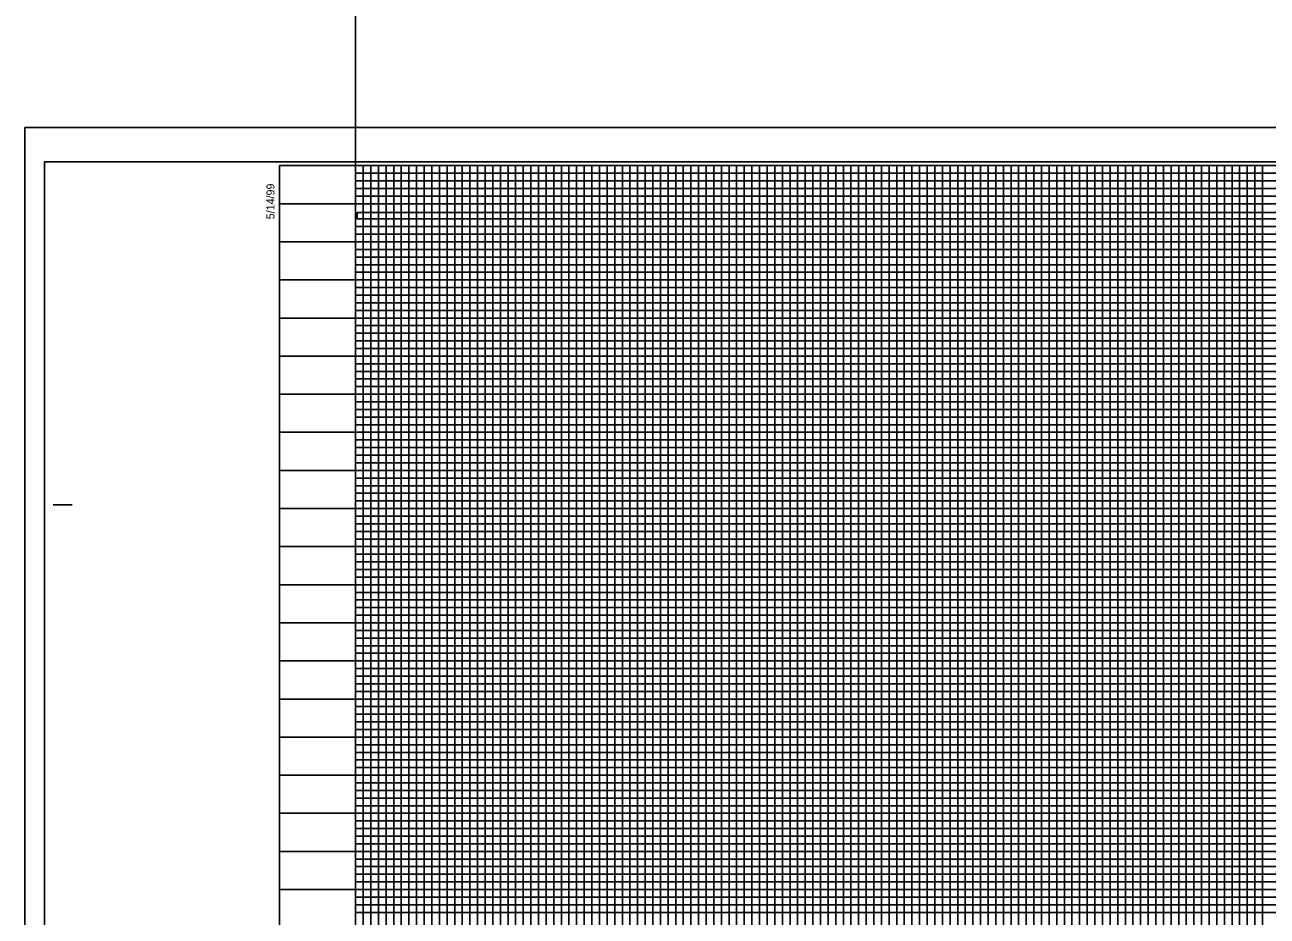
# Model space of a CAD drawing. Extents: x 2345490 to 2436403, y 465165 to 573888.
# Drawn here: x 2381550 to 2382365, y 506304 to 506889 of the extents above; entities that cross this region are included whole.
import ezdxf

# ---------------------------------------------------------------- set-up
doc = ezdxf.new("R2010")
doc.units = 0
for name, color, linetype in [('Old_Level_18', 7, 'Continuous'), ('Old_Level_41', 7, 'Continuous'), ('Old_Level_42', 7, 'Continuous'), ('Old_Level_43', 7, 'Continuous'), ('Old_Level_50', 7, 'Continuous'), ('Old_Level_51', 7, 'Continuous'), ('Old_Level_63', 7, 'Continuous')]:
    doc.layers.add(name, color=color, linetype=linetype)

msp = doc.modelspace()

# ---------------------------------------------------------------- linework, layer by layer
at = {"layer": 'Old_Level_18'}
msp.add_lwpolyline([(2383216.79875, 506796.2405), (2381716.79875, 506796.2405), (2381716.79875, 505746.2405), (2383216.79875, 505746.2405)], close=True, dxfattribs=at)
at = {"layer": 'Old_Level_41'}
msp.add_line((2381568.29875, 506573.7405), (2381580.79875, 506573.7405), dxfattribs=at)
for points in [[(2381716.79875, 506796.2405), (2381766.79875, 506796.2405), (2381766.79875, 505771.2405)], [(2381791.79875, 505771.2405), (2381791.79875, 506796.2405), (2381841.79875, 506796.2405), (2381841.79875, 505771.2405)], [(2381816.79875, 505771.2405), (2381816.79875, 506796.2405), (2381866.79875, 506796.2405), (2381866.79875, 505771.2405)], [(2381891.79875, 505771.2405), (2381891.79875, 506796.2405), (2381941.79875, 506796.2405), (2381941.79875, 505771.2405)], [(2381916.79875, 505771.2405), (2381916.79875, 506796.2405), (2381966.79875, 506796.2405), (2381966.79875, 505771.2405)], [(2381991.79875, 505771.2405), (2381991.79875, 506796.2405), (2382041.79875, 506796.2405), (2382041.79875, 505771.2405)], [(2382016.79875, 505771.2405), (2382016.79875, 506796.2405), (2382066.79875, 506796.2405), (2382066.79875, 505771.2405)], [(2382091.79875, 505771.2405), (2382091.79875, 506796.2405), (2382141.79875, 506796.2405), (2382141.79875, 505771.2405)], [(2382116.79875, 505771.2405), (2382116.79875, 506796.2405), (2382166.79875, 506796.2405), (2382166.79875, 505771.2405)], [(2382191.79875, 505771.2405), (2382191.79875, 506796.2405), (2382241.79875, 506796.2405), (2382241.79875, 505771.2405)], [(2382216.79875, 505771.2405), (2382216.79875, 506796.2405), (2382266.79875, 506796.2405), (2382266.79875, 505771.2405)], [(2382291.79875, 505771.2405), (2382291.79875, 506796.2405), (2382341.79875, 506796.2405), (2382341.79875, 505771.2405)], [(2382316.79875, 505771.2405), (2382316.79875, 506796.2405), (2382366.79875, 506796.2405)], [(2381716.79875, 506746.2405), (2383016.74875, 506746.2405)], [(2383016.74875, 506696.2405), (2381716.79875, 506696.2405), (2381716.79875, 506646.1905), (2383216.79875, 506646.1905)], [(2383216.79875, 506621.2405), (2381716.79875, 506621.2405), (2381716.79875, 506671.2405), (2383016.74875, 506671.2405)], [(2383216.79875, 506596.2405), (2381716.79875, 506596.2405), (2381716.79875, 506546.2405), (2383216.79875, 506546.2405)], [(2383216.79875, 506521.2405), (2381716.79875, 506521.2405), (2381716.79875, 506571.2405), (2383216.79875, 506571.2405)], [(2383216.79875, 506496.2405), (2381716.79875, 506496.2405), (2381716.79875, 506446.2405), (2383216.79875, 506446.2405)], [(2383216.79875, 506396.2405), (2381716.79875, 506396.2405), (2381716.79875, 506346.2405), (2383216.79875, 506346.2405)]]:
    msp.add_lwpolyline(points, dxfattribs=at)
at = {"layer": 'Old_Level_42'}
for points in [[(2383016.74875, 506721.2405), (2381716.89875, 506721.2405), (2381716.89875, 506771.1905), (2383016.74875, 506771.1905)], [(2383216.79875, 506421.2405), (2381716.79875, 506421.2405), (2381716.79875, 506471.2405), (2383216.79875, 506471.2405)], [(2383216.79875, 506321.2405), (2381716.79875, 506321.2405), (2381716.79875, 506371.2405), (2383216.79875, 506371.2405)]]:
    msp.add_lwpolyline(points, dxfattribs=at)
at = {"layer": 'Old_Level_43'}
for p, q in [((2383166.79875, 506616.2405), (2381766.79875, 506616.2405)), ((2381766.79875, 506616.2405), (2381766.79875, 506611.2405)), ((2381766.79875, 506611.2405), (2383166.79875, 506611.2405)), ((2383166.79875, 506591.2405), (2381766.79875, 506591.2405))]:
    msp.add_line(p, q, dxfattribs=at)
for points in [[(2381771.79875, 506796.2405), (2381776.79875, 506796.2405), (2381781.79875, 506796.2405), (2381786.79875, 506796.2405), (2381796.79875, 506796.2405), (2381763.74875, 506796.2405), (2381768.74875, 506796.2405), (2381726.79875, 506796.2405), (2381731.79875, 506796.2405), (2381736.79875, 506796.2405), (2381746.79875, 506796.2405), (2381751.79875, 506796.2405), (2381756.79875, 506796.2405), (2381761.79875, 506796.2405), (2381771.79875, 506796.2405), (2381771.79875, 505771.2405)], [(2383016.74875, 506791.2405), (2381766.79875, 506791.2405), (2381766.79875, 506786.2405), (2383016.74875, 506786.2405)], [(2381776.79875, 505771.2405), (2381776.79875, 506796.2405), (2381781.79875, 506796.2405), (2381781.79875, 505771.2405)], [(2381786.79875, 505771.2405), (2381786.79875, 506796.2405), (2381796.79875, 506796.2405), (2381796.79875, 505771.2405)], [(2381801.79875, 505771.2405), (2381801.79875, 506796.2405), (2381806.79875, 506796.2405), (2381806.79875, 505771.2405)], [(2381811.79875, 505771.2405), (2381811.79875, 506796.2405), (2381821.79875, 506796.2405), (2381821.79875, 505771.2405)], [(2381826.79875, 505771.2405), (2381826.79875, 506796.2405), (2381831.79875, 506796.2405), (2381831.79875, 505771.2405)], [(2381836.79875, 505771.2405), (2381836.79875, 506796.2405), (2381846.79875, 506796.2405), (2381846.79875, 505771.2405)], [(2381851.79875, 505771.2405), (2381851.79875, 506796.2405), (2381856.79875, 506796.2405), (2381856.79875, 505771.2405)], [(2381861.79875, 505771.2405), (2381861.79875, 506796.2405), (2381871.79875, 506796.2405), (2381871.79875, 505771.2405)], [(2381876.79875, 505771.2405), (2381876.79875, 506796.2405), (2381881.79875, 506796.2405), (2381881.79875, 505771.2405)], [(2381886.79875, 505771.2405), (2381886.79875, 506796.2405), (2381896.79875, 506796.2405), (2381896.79875, 505771.2405)], [(2381901.79875, 505771.2405), (2381901.79875, 506796.2405), (2381906.79875, 506796.2405), (2381906.79875, 505771.2405)], [(2381911.79875, 505771.2405), (2381911.79875, 506796.2405), (2381921.79875, 506796.2405), (2381921.79875, 505771.2405)], [(2381926.79875, 505771.2405), (2381926.79875, 506796.2405), (2381931.79875, 506796.2405), (2381931.79875, 505771.2405)], [(2381936.79875, 505771.2405), (2381936.79875, 506796.2405), (2381946.79875, 506796.2405), (2381946.79875, 505771.2405)], [(2381951.79875, 505771.2405), (2381951.79875, 506796.2405), (2381956.79875, 506796.2405), (2381956.79875, 505771.2405)], [(2381961.79875, 505771.2405), (2381961.79875, 506796.2405), (2381971.79875, 506796.2405), (2381971.79875, 505771.2405)], [(2381976.79875, 505771.2405), (2381976.79875, 506796.2405), (2381976.79875, 506796.2405), (2381981.79875, 506796.2405), (2381981.79875, 505771.2405)], [(2381986.79875, 505771.2405), (2381986.79875, 506796.2405), (2381996.79875, 506796.2405), (2381996.79875, 505771.2405)], [(2382001.79875, 505771.2405), (2382001.79875, 506796.2405), (2382006.79875, 506796.2405), (2382006.79875, 505771.2405)], [(2382011.79875, 505771.2405), (2382011.79875, 506796.2405), (2382021.79875, 506796.2405), (2382021.79875, 505771.2405)], [(2382026.79875, 505771.2405), (2382026.79875, 506796.2405), (2382031.79875, 506796.2405), (2382031.79875, 505771.2405)], [(2382036.79875, 505771.2405), (2382036.79875, 506796.2405), (2382046.79875, 506796.2405), (2382046.79875, 505771.2405)], [(2382051.79875, 505771.2405), (2382051.79875, 506796.2405), (2382056.79875, 506796.2405), (2382056.79875, 505771.2405)], [(2382061.79875, 505771.2405), (2382061.79875, 506796.2405), (2382071.79875, 506796.2405), (2382071.79875, 505771.2405)], [(2382076.79875, 505771.2405), (2382076.79875, 506796.2405), (2382081.79875, 506796.2405), (2382081.79875, 505771.2405)], [(2382086.79875, 505771.2405), (2382086.79875, 506796.2405), (2382096.79875, 506796.2405), (2382096.79875, 505771.2405)], [(2382101.79875, 506796.2405), (2382101.79875, 505771.2405), (2382106.79875, 505771.2405), (2382106.79875, 506796.2405)], [(2382101.79875, 506795.6405), (2382101.79875, 505771.2405), (2382106.79875, 505771.2405), (2382106.79875, 506795.6405)], [(2382111.79875, 505771.2405), (2382111.79875, 506796.2405), (2382121.79875, 506796.2405), (2382121.79875, 505771.2405)], [(2382126.79875, 505771.2405), (2382126.79875, 506796.2405), (2382131.79875, 506796.2405), (2382131.79875, 505771.2405)], [(2382136.79875, 505771.2405), (2382136.79875, 506796.2405), (2382146.79875, 506796.2405), (2382146.79875, 505771.2405)], [(2382151.79875, 505771.2405), (2382151.79875, 506796.2405), (2382156.79875, 506796.2405), (2382156.79875, 505771.2405)], [(2382161.79875, 505771.2405), (2382161.79875, 506796.2405), (2382171.79875, 506796.2405), (2382171.79875, 505771.2405)], [(2382176.79875, 505771.2405), (2382176.79875, 506796.2405), (2382181.79875, 506796.2405), (2382181.79875, 505771.2405)], [(2382186.79875, 505771.2405), (2382186.79875, 506796.2405), (2382196.79875, 506796.2405), (2382196.79875, 505771.2405)], [(2382201.79875, 505771.2405), (2382201.79875, 506796.2405), (2382206.79875, 506796.2405), (2382206.79875, 505771.2405)], [(2382211.79875, 505771.2405), (2382211.79875, 506796.2405), (2382221.79875, 506796.2405), (2382221.79875, 505771.2405)], [(2382226.79875, 505771.2405), (2382226.79875, 506796.2405), (2382231.79875, 506796.2405), (2382231.79875, 505771.2405)], [(2382236.79875, 505771.2405), (2382236.79875, 506796.2405), (2382246.79875, 506796.2405), (2382246.79875, 505771.2405)], [(2382251.79875, 506796.2405), (2382251.79875, 505771.2405), (2382256.79875, 505771.2405), (2382256.79875, 506796.2405), (2382261.79875, 506796.2405), (2382261.79875, 505771.2405), (2382271.79875, 505771.2405), (2382271.79875, 506796.2405), (2382276.79875, 506796.2405), (2382276.79875, 505771.2405), (2382281.79875, 505771.2405), (2382281.79875, 506796.2405), (2382286.79875, 506796.2405), (2382286.79875, 505771.2405)], [(2382296.79875, 505771.2405), (2382296.79875, 506796.2405), (2382301.79875, 506796.2405), (2382301.79875, 505771.2405)], [(2382306.79875, 505771.2405), (2382306.79875, 506796.2405), (2382311.79875, 506796.2405), (2382311.79875, 505771.2405)], [(2382321.79875, 505771.2405), (2382321.79875, 506796.2405), (2382326.79875, 506796.2405), (2382326.79875, 505771.2405)], [(2382331.79875, 505771.2405), (2382331.79875, 506796.2405), (2382336.79875, 506796.2405), (2382336.79875, 505771.2405)], [(2382346.79875, 505771.2405), (2382346.79875, 506796.2405), (2382351.79875, 506796.2405), (2382351.79875, 505771.2405)], [(2382356.79875, 505771.2405), (2382356.79875, 506796.2405), (2382361.79875, 506796.2405), (2382361.79875, 505771.2405)], [(2383016.74875, 506781.2405), (2381766.79875, 506781.2405), (2381766.79875, 506776.2405), (2383016.74875, 506776.2405)], [(2383016.74875, 506765.4905), (2381767.79875, 506765.4905), (2381767.79875, 506761.2405), (2383016.74875, 506761.2405)], [(2383016.74875, 506756.2405), (2381766.79875, 506756.2405), (2381766.79875, 506751.2405), (2383016.74875, 506751.2405)], [(2383016.74875, 506741.2405), (2381766.79875, 506741.2405), (2381766.79875, 506736.2405), (2383016.74875, 506736.2405)], [(2383016.74875, 506731.2405), (2381766.79875, 506731.2405), (2381766.79875, 506726.2405), (2383016.74875, 506726.2405)], [(2383016.74875, 506716.2405), (2381766.79875, 506716.2405), (2381766.79875, 506711.2405), (2383016.74875, 506711.2405)], [(2383016.74875, 506706.2405), (2381766.79875, 506706.2405), (2381766.79875, 506701.2405), (2383016.74875, 506701.2405)], [(2383016.74875, 506691.2405), (2381766.79875, 506691.2405), (2381766.79875, 506686.2405), (2383016.74875, 506686.2405)], [(2383016.74875, 506681.2405), (2381766.79875, 506681.2405), (2381766.79875, 506676.2405), (2383016.74875, 506676.2405)], [(2383016.74875, 506666.2405), (2381766.79875, 506666.2405), (2381766.79875, 506661.2405), (2383016.74875, 506661.2405)], [(2383166.79875, 506656.2405), (2381766.79875, 506656.2405), (2381766.79875, 506656.2405), (2381766.79875, 506636.2405), (2383166.79875, 506636.2405)], [(2381766.79875, 506651.2405), (2383166.79875, 506651.2405)], [(2383166.79875, 506641.2405), (2381766.79875, 506641.2405)], [(2383166.79875, 506631.2405), (2381766.79875, 506631.2405), (2381766.79875, 506626.2405), (2383166.79875, 506626.2405)], [(2383166.79875, 506606.2405), (2381766.79875, 506606.2405), (2381766.79875, 506601.2405), (2383166.79875, 506601.2405)], [(2383166.79875, 506586.2405), (2381766.79875, 506586.2405), (2381766.79875, 506581.2405), (2383166.79875, 506581.2405)], [(2383166.79875, 506576.2405), (2381766.79875, 506576.2405)], [(2381766.79875, 506566.2405), (2383166.79875, 506566.2405)], [(2383166.79875, 506561.2405), (2381766.79875, 506561.2405), (2381766.79875, 506556.2405), (2383166.79875, 506556.2405)], [(2383166.79875, 506551.2405), (2381766.79875, 506551.2405), (2381766.79875, 506541.2405), (2383166.79875, 506541.2405)], [(2383166.79875, 506536.2405), (2381766.79875, 506536.2405), (2381766.79875, 506531.2405), (2383166.79875, 506531.2405)], [(2383166.79875, 506526.2405), (2381766.79875, 506526.2405), (2381766.79875, 506516.2405), (2383166.79875, 506516.2405)], [(2383166.79875, 506511.2405), (2381766.79875, 506511.2405), (2381766.79875, 506506.2405), (2383166.79875, 506506.2405)], [(2383166.79875, 506501.2405), (2381766.79875, 506501.2405), (2381766.79875, 506491.2405), (2383166.79875, 506491.2405)], [(2383166.79875, 506486.2405), (2381766.79875, 506486.2405), (2381766.79875, 506481.2405), (2383166.79875, 506481.2405)], [(2383166.79875, 506476.2405), (2381766.79875, 506476.2405), (2381766.79875, 506466.2405), (2383166.79875, 506466.2405)], [(2383166.79875, 506461.2405), (2381766.79875, 506461.2405), (2381766.79875, 506456.2405), (2383166.79875, 506456.2405)], [(2383166.79875, 506451.2405), (2381766.79875, 506451.2405), (2381766.79875, 506441.2405), (2383166.79875, 506441.2405)], [(2383166.79875, 506436.2405), (2381766.79875, 506436.2405), (2381766.79875, 506431.2405), (2383166.79875, 506431.2405)], [(2383166.79875, 506426.2405), (2381766.79875, 506426.2405), (2381766.79875, 506416.2405), (2383166.79875, 506416.2405)], [(2383166.79875, 506411.2405), (2381766.79875, 506411.2405), (2381766.79875, 506406.2405), (2383166.79875, 506406.2405)], [(2383166.79875, 506401.2405), (2381766.79875, 506401.2405), (2381766.79875, 506391.2405), (2383166.79875, 506391.2405)], [(2383166.79875, 506386.2405), (2381766.79875, 506386.2405), (2381766.79875, 506381.2405), (2383166.79875, 506381.2405)], [(2383166.79875, 506376.2405), (2381766.79875, 506376.2405), (2381766.79875, 506366.2405), (2383166.79875, 506366.2405)], [(2383166.79875, 506361.2405), (2381766.79875, 506361.2405), (2381766.79875, 506356.2405), (2383166.79875, 506356.2405)], [(2383166.79875, 506351.2405), (2381766.79875, 506351.2405), (2381766.79875, 506341.2405), (2383166.79875, 506341.2405)], [(2383166.79875, 506336.2405), (2381766.79875, 506336.2405), (2381766.79875, 506331.2405), (2383166.79875, 506331.2405)], [(2383166.79875, 506326.2405), (2381766.79875, 506326.2405), (2381766.79875, 506316.2405), (2383166.79875, 506316.2405)], [(2383166.79875, 506311.2405), (2381766.79875, 506311.2405), (2381766.79875, 506306.2405), (2383166.79875, 506306.2405)]]:
    msp.add_lwpolyline(points, dxfattribs=at)
at = {"layer": 'Old_Level_50'}
msp.add_lwpolyline([(2383229.29875, 506798.7905), (2381562.79875, 506798.7905), (2381562.79875, 505743.6905), (2383229.29875, 505743.6905)], close=True, dxfattribs=at)
at = {"layer": 'Old_Level_51'}
msp.add_lwpolyline([(2383233.79875, 506821.2405), (2381549.79875, 506821.2405), (2381549.79875, 505721.2405), (2383233.79875, 505721.2405)], close=True, dxfattribs=at)
at = {"layer": 'Old_Level_63'}
msp.add_line((2381766.79875, 505771.2405), (2381766.79875, 508271.2405), dxfattribs=at)

# ---------------------------------------------------------------- texts
at = {"layer": 'Old_Level_41'}
msp.add_text('5/14/99', height=5.25, rotation=90, dxfattribs=at).set_placement((2381713.54875, 506761.0405))

doc.saveas('drawing.dxf')
